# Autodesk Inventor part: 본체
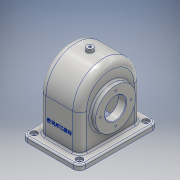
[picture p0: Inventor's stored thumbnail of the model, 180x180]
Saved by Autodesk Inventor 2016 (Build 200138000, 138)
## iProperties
Created: 2018-11
Part Number: 본체
Material: 알루미늄 6061
Document SubType Name: Modeling
Designer: user
Mass: 1091.92 g
Surface Area: 1182.48 cm^2
Volume: 404.417 cm^3
Density: 2.7 g/cm^3
Appearance: 알루미늄 - 평지
Author: user
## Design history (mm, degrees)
sketch "스케치1"
  geometry: C1 r 58 at (0, 0); 1 further point
  constraints: 1 centre point, 1 coincident
  dimensions: "d1" = 116 diameter of C1
extrude "돌출1" new body sketch "스케치1" stored distance "d2" = 77; taper "d3" = 0 deg
sketch "스케치2"
  geometry: L1 (-38.5, 58)-(-38.5, -58) reference; L2 (38.5, -58)-(38.5, 58) reference; L3 (-38.5, 58)-(38.5, 58); L4 (38.5, 58)-(38.5, -58); L5 (38.5, -58)-(-38.5, -58); L6 (-38.5, -58)-(-38.5, 58); 1 further point
  constraints: 8 end point, 2 parallel, 1 horizontal, 1 perpendicular
extrude "돌출2" join sketch "스케치2" distance "d4" = 78; taper "d5" = 0 deg
sketch "스케치3"
  geometry: L1 (38.5, 58)-(-38.5, 58) reference; L2 (-38.5, 58)-(-38.5, -58) reference; L3 (-38.5, -58)-(38.5, -58) reference; L4 (38.5, -58)-(38.5, 58) reference; L5 (55, -75)-(-55, -75); L6 (-55, -75)-(-55, 75); L7 (-55, 75)-(55, 75); L8 (55, 75)-(55, -75); L9 (55, -75)-(-55, 75); L10 (-55, -75)-(55, 75); 1 further point
  constraints: 12 end point, 2 midpoint, 2 parallel, 1 horizontal, 1 perpendicular
  dimensions: "d6" = 110 distance of L6.end L7.end; "d7" = 150 distance of L5.end L6.end
  node "투영된 루프1"
feature "쉘1" dims "d8" = 6, "d77" = 5
extrude "돌출3" join sketch "스케치3" distance "d9" = 10; taper "d10" = 0 deg
node "작업 평면1"
sketch "스케치4"
  geometry: L1 (38.5, 58)-(-38.5, 58) reference; L2 (38.5, -58)-(38.5, 58) reference; L3 (38.5, -58)-(-38.5, -58) reference; L4 (-38.5, 58)-(-38.5, -58) reference; L5 (-38.5, -58)-(-38.5, 58) reference; L6 (38.5, -58)-(-38.5, -58) reference; L7 (38.5, 58)-(38.5, -58) reference; L8 (-38.5, 58)-(38.5, 58) reference; L9 (55, -75)-(-55, -75) reference; L10 (-55, -75)-(-55, 75) reference; L11 (-55, 75)-(55, 75) reference; L12 (55, 75)-(55, -75) reference; C1 r 6 at (0, 0); 1 further point
  constraints: 1 centre point, 1 coincident
  dimensions: "d12" = 12 diameter of C1
extrude "돌출4" join sketch "스케치4" stored distance "d13" = 5; taper "d14" = 5 deg
sketch "스케치5"
  geometry: L1 (68, -58)-(68, 58) reference; L2 (0, 58)-(68, 58) reference; L3 (0, -58)-(68, -58) reference; L4 (78, -75)-(78, 75) reference; C1 r 38 at (13, 0); A1 r 58 centre (0, 0) between (0, 58) and (0, -58) reference; A2 r 58 centre (0, 0) between (0, 58) and (0, -58) reference; 2 further points
  constraints: 1 centre point, 1 horizontal alignment, 1 point on circle
  dimensions: "d17" = 76 diameter of C1; "d18" = 65 distance from line of L4 C1.centre
extrude "돌출5" join sketch "스케치5" distance "d19" = 10; taper "d20" = 0 deg
sketch "스케치6"
  geometry: C1 r 38 at (-13, 0) reference; 1 further point
extrude "돌출6" join sketch "스케치6" distance "d21" = 5; taper "d22" = 0 deg
sketch "스케치7"
  geometry: L1 (33.5, 0)-(-33.5, 0) reference; L2 (33.5, 0)-(33.5, -78) reference; L3 (-33.5, -78)-(33.5, -78) reference; L4 (-33.5, 0)-(-33.5, -78) reference; L5 (33.5, 0)-(-33.5, 0) reference; L6 (-33.5, 0)-(-33.5, 0) reference; L7 (33.5, 0)-(-33.5, 0) reference; L8 (33.5, 0)-(33.5, 0) reference; L9 (33.5, 0)-(33.5, 52) reference; L10 (-33.5, 52)-(-33.5, 0) reference; L11 (43.5, -51)-(43.5, 25) reference; L12 (19.5, 15)-(19.5, -13); L13 (38.5, 0)-(38.5, -68) reference; L14 (19.5, 15)-(33.5, 26.747); L15 (19.5, -13)-(33.5, -13); L16 (33.5, 26.747)-(33.5, -13); L17 (33.5, 0)-(33.5, -78) reference; 1 further point
  constraints: 8 end point, 2 point on line, 1 collinear, 1 parallel, 1 perpendicular
  dimensions: "d23" = 28 distance of L12.start L12.end; "d25" = 24 distance between parallel lines of L12 L11; "d26" = 50 deg angle of L14 L12
revolve "회전1" sketch "스케치7" stored, may be unused: angle "d27" = 90 deg
fillet "모깎기1" dims "d28" = 3
sketch "스케치8"
  geometry: C1 r 38 at (0, 0) reference; 2 further points
  constraints: 1 coincident
hole "구멍1" sketch "스케치8" at (0, 0) diameter "d29" = 40; stored, may be unused: countersink angle "d33" = 90 deg, drill point angle "d35" = 118 deg; dims "d30" = 6, "d31" = 4, "d32" = 2, "d34" = 8
sketch "스케치9"
  geometry: C1 r 6 at (0, 0) reference; 2 further points
  constraints: 1 coincident
hole "구멍2" sketch "스케치9" at (0, 0) diameter "d36" = 4.459; stored, may be unused: countersink angle "d40" = 90 deg, drill point angle "d42" = 118 deg; dims "d37" = 30, "d38" = 4, "d39" = 2, "d41" = 12.8
fillet "모깎기2" dims "d43" = 13
fillet "모깎기3" dims "d44" = 3
fillet "모깎기4" dims "d45" = 8
fillet "모깎기5" dims "d46" = 12
fillet "모깎기6" dims "d47" = 3
sketch "스케치10"
  geometry: L1 (43, 75)-(-43, 75) reference; L2 (55, -63)-(55, 63) reference; L3 (-43, -75)-(43, -75) reference; L4 (-55, 63)-(-55, -63) reference; L5 (25.5, 52)-(-25.5, 52) reference; L6 (-33.5, 44)-(-33.5, -44) reference; L7 (-25.5, -52)-(25.5, -52) reference; L8 (33.5, -44)-(33.5, 44) reference; A1 r 12 centre (-43, 63) between (-43, 75) and (-55, 63) reference; A2 r 12 centre (43, 63) between (55, 63) and (43, 75) reference; A3 r 12 centre (43, -63) between (43, -75) and (55, -63) reference; A4 r 12 centre (-43, -63) between (-55, -63) and (-43, -75) reference; A5 r 8 centre (-25.5, 44) between (-25.5, 52) and (-33.5, 44) reference; A6 r 8 centre (-25.5, -44) between (-33.5, -44) and (-25.5, -52) reference; A7 r 8 centre (25.5, -44) between (25.5, -52) and (33.5, -44) reference; A8 r 8 centre (25.5, 44) between (33.5, 44) and (25.5, 52) reference; 5 further points
  constraints: 4 coincident
hole "구멍3" sketch "스케치10" at (-43, 63), (43, 63), (43, -63), (-43, -63) diameter "d48" = 5; stored, may be unused: countersink angle "d52" = 90 deg, drill point angle "d54" = 118 deg; dims "d49" = 30, "d50" = 12, "d51" = 4, "d53" = 12.8
sketch "스케치11"
  geometry: C1 r 20 at (0, 0) reference; C2 r 38 at (0, 0) reference; A1 r 29 centre (0, 0) between (-29, 0) and (0, 29); 3 further points
  constraints: 4 point on circle, 1 centre point, 1 coincident
  dimensions: "d55" = 58 diameter of A1
hole "구멍4" sketch "스케치11" at (-29, 0), (0, 29), (0, -29), (29, 0) diameter "d56" = 3.242; stored, may be unused: countersink angle "d60" = 90 deg, drill point angle "d62" = 118 deg; dims "d57" = 8, "d58" = 19.05, "d59" = 4.775, "d61" = 10
sketch "스케치12"
  geometry: L1 (0, 0)-(0, 68) reference; L2 (0, 0)-(51, 0) reference; L3 (51, 68)-(51, 0) reference; L4 (0, 68)-(51, 68) reference; L5 (-17.5, -3)-(68.5, -3) reference; L6 (-17.5, -10)-(-17.5, -3) reference; L7 (-17.5, -10)-(68.5, -10) reference; L8 (68.5, -3)-(68.5, -10) reference; L9 (-13, 0)-(0, 0) reference; L10 (0, 0)-(0, 68) reference; L11 (-13, 68)-(0, 68) reference; L12 (-13, 68)-(-13, 0) reference; 2 further points
  constraints: 1 other
  dimensions: "d64" = 38.5 distance from line of L12 point (25.5, 30); "d65" = 40 distance from line of L7 point (25.5, 30)
feature "엠보싱1" sketch "스케치12" dims "d6" = 110, "d7" = 150, "d66" = 0.5, "d67" = 0
sketch "스케치13"
  geometry: C1 r 20 at (0, 0) reference; C2 r 38 at (0, 0) reference; A1 r 29 centre (0, 0) between (29, 0) and (0, -29); 3 further points
  constraints: 4 point on circle, 1 centre point, 1 coincident
  dimensions: "d68" = 58 diameter of A1
hole "구멍5" sketch "스케치13" at (29, 0), (0, -29), (0, 29), (-29, 0) diameter "d69" = 3.242; stored, may be unused: countersink angle "d73" = 90 deg, drill point angle "d75" = 118 deg; dims "d70" = 8, "d71" = 4, "d72" = 2, "d74" = 10
fillet "모깎기7" dims "d76" = 3
chamfer "모따기1" distance "d78" = 1; stored, may be unused: second distance "d79" = 2, angle "d80" = 45 deg
chamfer "모따기2" distance "d81" = 1; stored, may be unused: second distance "d82" = 2, angle "d83" = 45 deg
node "솔리드1"
node "투영된 루프2"
node "투영된 루프3"
node "투영된 루프4"
node "투영된 루프5"
node "투영된 루프6"
node "투영된 루프7"
node "투영된 루프8"
node "투영된 루프9"
node "투영된 루프10"
node "투영된 루프11"
node "투영된 루프12"
node "투영된 루프13"
node "투영된 루프14"
other parameters: "d11" = -142
